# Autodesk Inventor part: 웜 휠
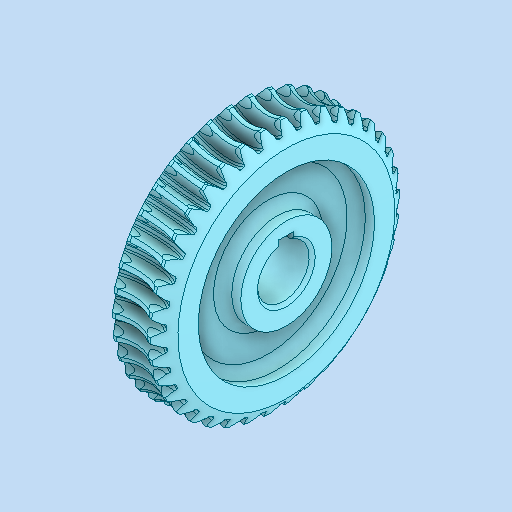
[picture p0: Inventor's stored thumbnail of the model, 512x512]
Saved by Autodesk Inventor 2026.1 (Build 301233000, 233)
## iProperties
Created: 2026-01
Part Number: 웜 휠
Material: 강철, 합금
Document SubType Name: Modeling
Designer: PC-30
Density: 7.73 g/cm^3
Appearance: 기본값
Author: jhkim
Sending System: Autodesk Inventor 2026
Preprocessor: ST-DEVELOPER v20.1
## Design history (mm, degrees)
feature "솔리드1"
node "솔리드2"
